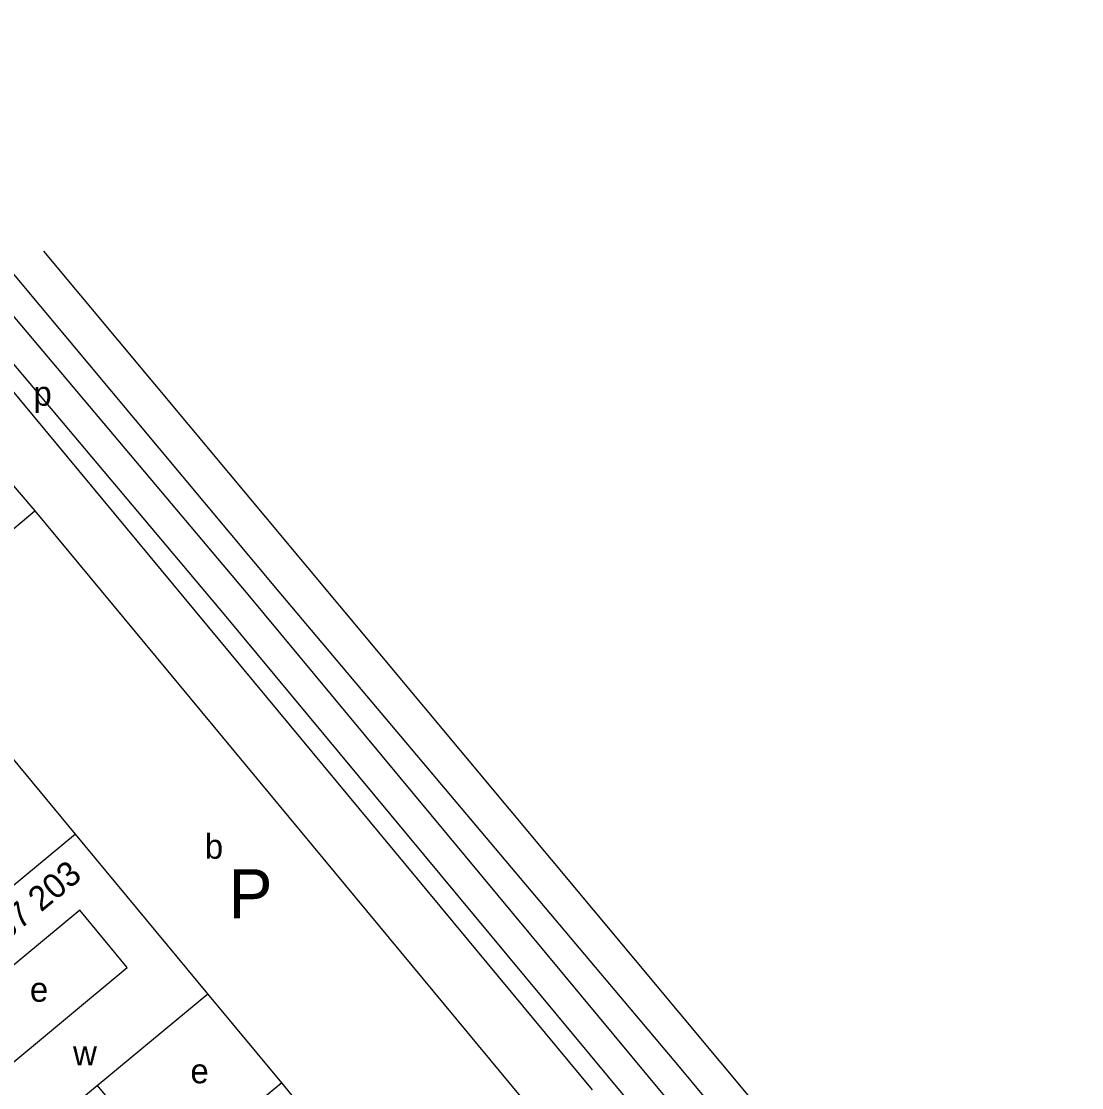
# Model space of a CAD drawing. Extents: x 159261 to 160849, y 382514 to 384534.
# Drawn here: x 160141.9 to 160314.3, y 384110.1 to 384283.5 of the extents above; entities that cross this region are included whole.
import ezdxf

# ---------------------------------------------------------------- set-up
doc = ezdxf.new("R2010")
doc.units = 0
for name, color, linetype in [('BLT_Basislijn', 7, 'Continuous'), ('BLT_Bebouwing', 7, 'Continuous'), ('BLT_Centroide', 7, 'Continuous'), ('BLT_Huisnummer_reeks', 7, 'Continuous'), ('BLT_Onderverdeling_panden', 7, 'Continuous'), ('BLT_Spoorlijn', 7, 'Continuous'), ('BLT_Tekst_parkeren', 7, 'Continuous')]:
    doc.layers.add(name, color=color, linetype=linetype)

msp = doc.modelspace()

# ---------------------------------------------------------------- linework, layer by layer
at = {"layer": 'BLT_Basislijn'}
msp.add_line((160118.37, 384250), (160234.74, 384109.69), dxfattribs=at)
for points in [[(160118.37, 384250), (160131.67, 384238.31), (160174.89, 384187.05)], [(160126.94, 384222.87), (160127.44, 384223.3), (160144.08, 384203.86)], [(160174.89, 384187.05), (160242.64, 384105.44), (160259.57, 384085.26)], [(160154.2, 384110.43), (160159.52, 384104.01), (160157.58, 384102.4), (160165.55, 384092.77)]]:
    msp.add_lwpolyline(points, dxfattribs=at)
at = {"layer": 'BLT_Bebouwing'}
for p, q in [((160138.24, 384199.02), (160144.08, 384203.86)), ((160144.08, 384203.86), (160227.28, 384103.58)), ((160150.69, 384151.3), (160136.49, 384168.43)), ((160150.69, 384151.3), (160128.3, 384132.77)), ((160172.2, 384125.34), (160150.69, 384151.3)), ((160154.2, 384110.43), (160172.2, 384125.34)), ((160184.23, 384110.83), (160172.2, 384125.34))]:
    msp.add_line(p, q, dxfattribs=at)
msp.add_lwpolyline([(160151.39, 384138.91), (160130.29, 384121.41), (160138, 384112.11), (160159.1, 384129.62)], close=True, dxfattribs=at)
for points in [[(160128.3, 384132.77), (160115.17, 384121.9), (160139.27, 384098.07), (160154.2, 384110.43)], [(160184.23, 384110.83), (160176.32, 384104.27), (160177.6, 384102.75), (160165.55, 384092.77)]]:
    msp.add_lwpolyline(points, dxfattribs=at)
at = {"layer": 'BLT_Onderverdeling_panden'}
msp.add_line((160205.3, 384085.42), (160184.23, 384110.83), dxfattribs=at)
at = {"layer": 'BLT_Spoorlijn'}
msp.add_line((160248.87, 384113.45), (160314.32, 384034.57), dxfattribs=at)
for points in [[(160100.1, 384283.51), (160178.72, 384190.28)], [(160106.17, 384283.51), (160183.5, 384191.02)], [(160145.48, 384246.1), (160193.63, 384188.43)], [(160183.5, 384191.02), (160248.87, 384113.45)], [(160178.72, 384190.28), (160246.47, 384108.66)], [(160193.63, 384188.43), (160262.49, 384105.89)]]:
    msp.add_lwpolyline(points, dxfattribs=at)

# ---------------------------------------------------------------- texts
at = {"layer": 'BLT_Centroide'}
for s, p in [('p', (160143.86, 384220.98)), ('b', (160171.73, 384147.3)), ('e', (160143.29, 384124.04)), ('w', (160150.31, 384113.69)), ('e', (160169.39, 384110.77))]:
    msp.add_text(s, height=4, dxfattribs=at).set_placement(p)
at = {"layer": 'BLT_Huisnummer_reeks'}
msp.add_text('67 01 t/m 67 203', height=4, rotation=39.6073, dxfattribs=at).set_placement((160121.04, 384118.62))
at = {"layer": 'BLT_Tekst_parkeren'}
msp.add_text('P', height=8, dxfattribs=at).set_placement((160175.6, 384137.6))

doc.saveas('drawing.dxf')
